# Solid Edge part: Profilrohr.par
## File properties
Username: bmolnar
Dokumentum tartalom típus: 0
Author: bmolnar
Last saved by: bmolnar
Revision: 84
Sűrűség: 0,000 kg/m^3
Pontosság: 0,990
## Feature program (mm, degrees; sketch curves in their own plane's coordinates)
base feature "unnamed BaseFeature 1"
thread "unnamed Thread 1"
thread "Menet_2"  ThreadDepth = 6 mm
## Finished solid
Body 1: solid body, 157 faces, 388 edges, 253 vertices.
  Faces by surface: plane 102, cylinder 41, cone 8, torus 6
  Edges by curve: line 284, circle 92, curve on surface 7, spline 4, intersection 1
Bounding box of the edges (mm; curved faces can reach further): 55.000 x 58.000 x 79.500, from (-27.5, -27.5, 0) to (27.5, 30.5, 79.5).
Cylindrical faces by radius (mm): R1.125 x2, R2.9 x8, R4.283 x4, R4.4 x16, R20 x1, R20.85 x2, R21.1 x2, R22.35 x2, R36.5 x4
Conical faces (half-angle, radius in mm at the cone's reference point): 30 deg R20.325 x2, 45 deg R4.783 x2, 45 deg R21.1 x2, 45 deg R21.35 x2
Toroidal faces (ring radius, tube radius in mm): R20.75 r0.1 x2, R22.15 r0.2 x4
Planar faces by outward normal: +x 9, +y 11, +z 8, -x 9, -y 9, -z 8, oblique 48
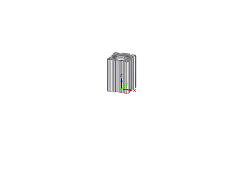
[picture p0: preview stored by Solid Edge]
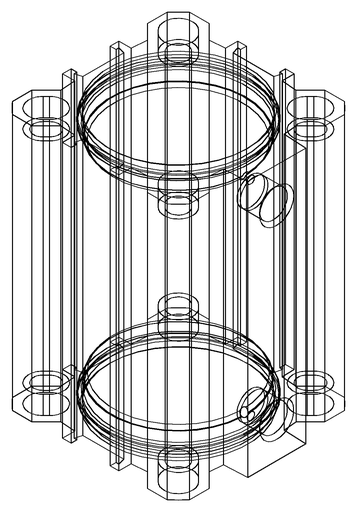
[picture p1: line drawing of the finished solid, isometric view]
